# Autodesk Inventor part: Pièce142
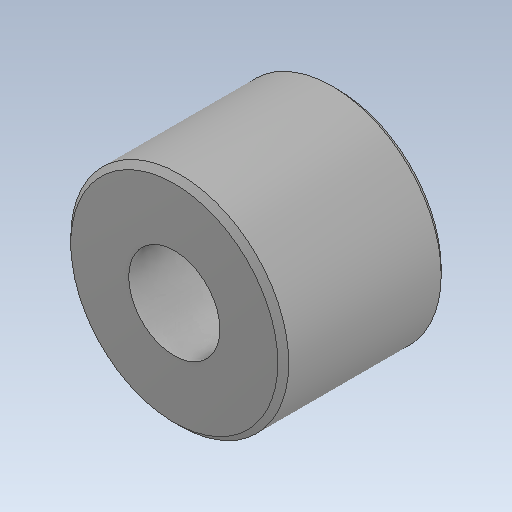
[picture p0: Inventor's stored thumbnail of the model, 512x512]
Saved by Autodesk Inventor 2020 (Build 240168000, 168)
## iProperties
Created: 2022-10
Part Number: Pièce142
Material: Générique
Document SubType Name: Modeling
Designer: bruno
Density: 1 g/cm^3
Appearance: Par défaut
Author: bruno
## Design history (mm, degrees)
feature "Base1"
node "Solide1"
